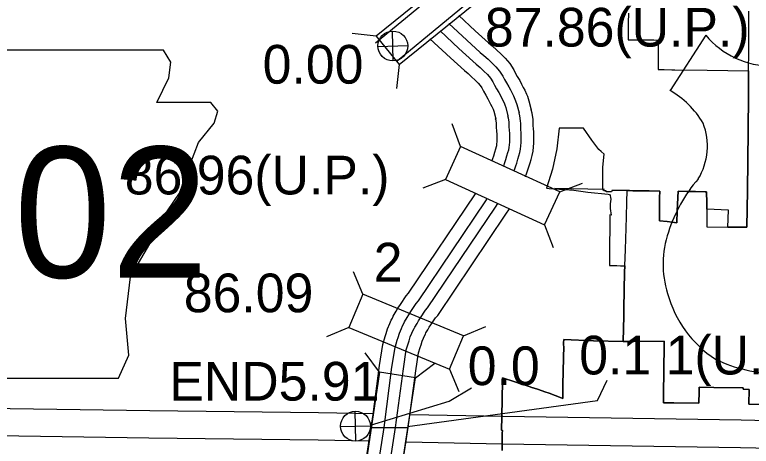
# Model space of a CAD drawing. Extents: x 77230 to 630905, y 790554 to 1662844.
# Drawn here: x 233840 to 249911, y 1585968 to 1595386 of the extents above; entities that cross this region are included whole.
import ezdxf

# ---------------------------------------------------------------- set-up
doc = ezdxf.new("R2010")
doc.units = 0
for name, color, linetype in [('Level 12', 7, 'Continuous'), ('Level 16', 7, 'Continuous'), ('Level 19', 7, 'Continuous'), ('Level 22', 7, 'Continuous'), ('Level 23', 7, 'Continuous'), ('Level 24', 7, 'Continuous'), ('Level 25', 7, 'Continuous'), ('Level 29', 7, 'Continuous'), ('Level 31', 7, 'Continuous'), ('Level 32', 7, 'Continuous'), ('Level 34', 7, 'Continuous')]:
    doc.layers.add(name, color=color, linetype=linetype)

msp = doc.modelspace()

# ---------------------------------------------------------------- linework, layer by layer
at = {"layer": 'Level 12'}
for points in [[(247229, 1595417), (247225, 1595210), (247225, 1594841), (247770, 1594836), (247783, 1594836), (247847, 1594834), (247882, 1594835), (247882, 1594189), (248012, 1594188), (248177, 1594185), (248242, 1594185), (248950, 1594173), (249851, 1594159), (249851, 1594021), (249848, 1593627), (249841, 1592853), (249831, 1591548), (249814, 1590748), (249401, 1590750), (249413, 1591121), (248943, 1591146), (248940, 1591278), (248934, 1591522), (248907, 1591522), (248698, 1591526), (248509, 1591529), (248314, 1591532), (248314, 1591532), (248297, 1591103), (248285, 1590847), (248188, 1590862), (248075, 1590872), (247906, 1590885), (247907, 1590919), (247907, 1590990), (247909, 1591118), (247910, 1591193), (247910, 1591268), (247912, 1591390), (247913, 1591539), (247681, 1591542), (247554, 1591543), (247479, 1591544), (247404, 1591545)], [(249831, 1591548), (249841, 1592853), (249848, 1593627), (249851, 1594021), (249851, 1594159), (249855, 1594592), (249860, 1595269), (249861, 1595465)], [(247404, 1591545), (247329, 1591546), (247254, 1591547), (247207, 1591548), (247179, 1591548), (247104, 1591549), (247029, 1591550), (246954, 1591551), (246866, 1591552), (246866, 1591544), (246865, 1591520), (246828, 1591520), (246747, 1591521), (246747, 1591543), (246701, 1591543), (246688, 1591559), (246674, 1591577), (246671, 1592002), (246671, 1592006), (246671, 1592061), (246699, 1592344), (246635, 1592402), (246582, 1592448), (246430, 1592651), (246250, 1592907), (246122, 1592907), (245865, 1592907), (245718, 1592909), (245669, 1592462), (245577, 1592017), (245441, 1591603), (245502, 1591597), (245846, 1591573), (245944, 1591567), (245992, 1591565), (246191, 1591532), (246347, 1591512), (246788, 1591467), (246817, 1591463), (246833, 1591441), (246842, 1591395), (246845, 1591363), (246833, 1591262), (246834, 1591159), (246853, 1591015), (246828, 1591017), (246826, 1590909), (246825, 1590829), (246824, 1590750), (246823, 1590670), (246822, 1590590), (246821, 1590510), (246820, 1590430), (246819, 1590350), (246818, 1590270), (246817, 1590190), (246817, 1590110), (246816, 1590030), (246815, 1589950), (246815, 1589914), (246895, 1589912), (246954, 1589911), (246975, 1589911), (247055, 1589909), (247150, 1589905), (247144, 1589767), (247144, 1589717), (247142, 1589618), (247141, 1589538), (247139, 1589458), (247138, 1589378), (247137, 1589298), (247135, 1589218), (247134, 1589138), (247132, 1589058), (247131, 1588978), (247130, 1588940), (247130, 1588898), (247128, 1588818), (247118, 1588255), (246466, 1588270), (245821, 1588296), (245817, 1588223), (245818, 1588093), (245812, 1587953), (245813, 1587823), (245807, 1587671), (245804, 1587526), (245801, 1587388), (245797, 1587013), (245766, 1587026), (245505, 1587128), (245410, 1587159), (245269, 1587205), (245155, 1587242), (245147, 1587245), (245041, 1587280), (244902, 1587325), (244895, 1587327), (244733, 1587380)], [(250223, 1586879), (249861, 1586887), (249867, 1587206), (249735, 1587212), (249736, 1587244), (249095, 1587254), (248773, 1587259), (248773, 1587231), (248772, 1587161), (248768, 1586906), (248225, 1586917), (247995, 1586919), (247996, 1587026), (247997, 1587161), (247998, 1587296), (248000, 1587431), (248002, 1587564), (248003, 1587699), (248006, 1587835), (248008, 1587969), (248009, 1588107), (248010, 1588265), (247351, 1588253), (247118, 1588255), (247128, 1588818), (247130, 1588898), (247130, 1588940), (247131, 1588978), (247132, 1589058), (247134, 1589138), (247135, 1589218), (247137, 1589298), (247138, 1589378), (247139, 1589458), (247141, 1589538), (247142, 1589618), (247144, 1589717), (247144, 1589767), (247150, 1589905), (247166, 1590259), (247181, 1590727), (247189, 1590977), (247199, 1591298), (247207, 1591548), (247254, 1591547), (247329, 1591546), (247404, 1591545), (247479, 1591544), (247554, 1591543), (247681, 1591542), (247913, 1591539), (247912, 1591390), (247910, 1591268), (247910, 1591193), (247909, 1591118), (247907, 1590990), (247907, 1590919), (247906, 1590885), (248075, 1590872), (248188, 1590862), (248285, 1590847), (248297, 1591103), (248314, 1591532), (248314, 1591532), (248509, 1591529), (248698, 1591526), (248907, 1591522), (248934, 1591522), (248940, 1591278), (248943, 1591146), (248943, 1591103), (248942, 1590973), (248940, 1590758), (249401, 1590750), (249814, 1590748), (249831, 1591548)], [(245807, 1587671), (245813, 1587823), (245812, 1587953), (245818, 1588093), (245817, 1588223), (245821, 1588296), (246466, 1588270), (247118, 1588255), (247351, 1588253), (248010, 1588265), (248009, 1588107), (248008, 1587969), (248006, 1587835), (248003, 1587699), (248002, 1587564), (248000, 1587431), (247998, 1587296), (247997, 1587161), (247996, 1587026), (247995, 1586919), (248225, 1586917), (248768, 1586906), (248772, 1587161), (248773, 1587231), (248773, 1587259), (249095, 1587254), (249736, 1587244), (249735, 1587212), (249867, 1587206), (249861, 1586887), (250223, 1586879)], [(244473, 1585878), (244475, 1585984), (244479, 1586255), (244480, 1586316), (244459, 1586317), (244466, 1586618), (244483, 1587389), (244484, 1587461), (244504, 1587455), (244733, 1587380), (244895, 1587327), (244902, 1587325), (245041, 1587280), (245147, 1587245), (245155, 1587242), (245269, 1587205), (245410, 1587159), (245505, 1587128), (245766, 1587026), (245797, 1587013), (245801, 1587388), (245804, 1587526), (245807, 1587671)], [(244733, 1587380), (244504, 1587455), (244484, 1587461), (244483, 1587389), (244466, 1586618), (244459, 1586317), (244480, 1586316), (244479, 1586255), (244475, 1585984), (244473, 1585878)]]:
    msp.add_lwpolyline(points, dxfattribs=at)
at = {"layer": 'Level 16'}
msp.add_lwpolyline([(246706, 1591573), (245626, 1591590)], dxfattribs=at)
at = {"layer": 'Level 19'}
for p, q in [((241729, 1594918), (241204, 1594973)), ((242228, 1594303), (242174, 1593778)), ((243570, 1592509), (243385, 1593004)), ((243570, 1592509), (243385, 1593004)), ((243241, 1591789), (242746, 1591604)), ((243241, 1591789), (242746, 1591604)), ((245731, 1591522), (246226, 1591707)), ((245731, 1591522), (246226, 1591707)), ((245402, 1590802), (245587, 1590307)), ((241437, 1589289), (241235, 1589777)), ((241134, 1588557), (240646, 1588355)), ((243632, 1588380), (244120, 1588582)), ((241800, 1587583), (241486, 1588007)), ((242583, 1587465), (243008, 1587779)), ((243329, 1587648), (243532, 1587160))]:
    msp.add_line(p, q, dxfattribs=at)
for points in [[(242228, 1594303), (244074, 1595800), (243575, 1596415), (241729, 1594918)], [(243241, 1591789), (245402, 1590802), (245731, 1591522), (243570, 1592509)], [(243632, 1588380), (241437, 1589289), (241134, 1588557), (243329, 1587648)], [(241800, 1587583), (241448, 1585233), (242231, 1585116), (242583, 1587465)]]:
    msp.add_lwpolyline(points, close=True, dxfattribs=at)
at = {"layer": 'Level 22'}
for points in [[(241711, 1594769), (243884, 1596567)], [(242182, 1594380), (244092, 1595960)], [(236791, 1586745), (232215, 1586809)], [(241662, 1586674), (240472, 1586698), (236791, 1586745)], [(257681, 1586377), (255038, 1586411), (252389, 1586475), (249688, 1586535), (244488, 1586615), (242468, 1586657)], [(236770, 1586145), (232508, 1586208), (232304, 1586209), (231553, 1586212)], [(241555, 1586076), (240462, 1586098), (236770, 1586145)], [(257374, 1585781), (255027, 1585811), (252375, 1585875), (249677, 1585935), (244477, 1586015), (242381, 1586059)]]:
    msp.add_lwpolyline(points, dxfattribs=at)
at = {"layer": 'Level 23'}
msp.add_lwpolyline([(241620, 1586379), (241663, 1586658)], dxfattribs=at)
at = {"layer": 'Level 24'}
msp.add_lwpolyline([(230240, 1594615), (230582, 1592331), (230430, 1588867), (230735, 1588677), (231306, 1588677), (231306, 1587458), (236102, 1587458), (236330, 1587953), (236254, 1588753), (236368, 1589666), (236787, 1590389), (237053, 1590922), (237434, 1591493), (237663, 1592102), (237853, 1592597), (238195, 1593016), (238272, 1593282), (238119, 1593473), (236939, 1593473), (237206, 1594006), (237244, 1594348), (237086, 1594611)], close=True, dxfattribs=at)
at = {"layer": 'Level 25'}
msp.add_line((248918, 1594939), (248139, 1593735), dxfattribs=at)
for centre, radius, start, end in [((250369, 1596159), 1896, 220.075, 319.6701), ((247121, 1591986), 2024, 30.7809, 59.9883), ((247567, 1592520), 1387, 328.8105, 21.2108), ((251194, 1589676), 3236, 138.9565, 162.6913), ((250126, 1589941), 2138, 160.9576, 197.3819), ((250474, 1589947), 2474, 195.1074, 237.1312), ((250520, 1590727), 3177, 244.0771, 269.5779)]:
    msp.add_arc(centre, radius, start, end, dxfattribs=at)
at = {"layer": 'Level 29'}
for points in [[(243531, 1595366), (243888, 1595034), (244179, 1594771), (244259, 1594704), (244358, 1594614), (244444, 1594530), (244538, 1594439), (244641, 1594318), (244727, 1594184), (244768, 1594102), (244806, 1594038), (244859, 1593950), (244901, 1593874), (244936, 1593800), (244968, 1593741), (245009, 1593650), (245027, 1593605), (245061, 1593506), (245110, 1593310)], [(243531, 1595366), (243888, 1595034), (244179, 1594771), (244259, 1594704), (244358, 1594614), (244444, 1594530), (244538, 1594439), (244641, 1594318), (244727, 1594184), (244768, 1594102), (244806, 1594038), (244859, 1593950), (244901, 1593874), (244936, 1593800), (244968, 1593741), (245009, 1593650), (245027, 1593605), (245061, 1593506), (245110, 1593310)], [(243313, 1595194), (243703, 1594831), (243998, 1594564), (244077, 1594497), (244170, 1594413), (244252, 1594333), (244337, 1594250), (244420, 1594154), (244487, 1594048), (244527, 1593969), (244571, 1593897), (244620, 1593814), (244656, 1593749), (244691, 1593675), (244722, 1593619), (244756, 1593542), (244769, 1593510), (244797, 1593428), (244844, 1593243)], [(243313, 1595194), (243703, 1594831), (243998, 1594564), (244077, 1594497), (244170, 1594413), (244252, 1594333), (244337, 1594250), (244420, 1594154), (244487, 1594048), (244527, 1593969), (244571, 1593897), (244620, 1593814), (244656, 1593749), (244691, 1593675), (244722, 1593619), (244756, 1593542), (244769, 1593510), (244797, 1593428), (244844, 1593243)], [(243120, 1595032), (243534, 1594647), (243834, 1594376), (243912, 1594309), (243998, 1594231), (244078, 1594154), (244155, 1594079), (244219, 1594005), (244270, 1593924), (244308, 1593848), (244356, 1593768), (244403, 1593689), (244433, 1593635), (244468, 1593561), (244498, 1593507), (244526, 1593444), (244535, 1593423), (244557, 1593358), (244601, 1593181)], [(243120, 1595032), (243534, 1594647), (243834, 1594376), (243912, 1594309), (243998, 1594231), (244078, 1594154), (244155, 1594079), (244219, 1594005), (244270, 1593924), (244308, 1593848), (244356, 1593768), (244403, 1593689), (244433, 1593635), (244468, 1593561), (244498, 1593507), (244526, 1593444), (244535, 1593423), (244557, 1593358), (244601, 1593181)], [(242901, 1594860), (243348, 1594444), (243652, 1594169), (243731, 1594103), (243810, 1594031), (243886, 1593957), (243954, 1593890), (243997, 1593840), (244030, 1593788), (244067, 1593715), (244120, 1593627), (244165, 1593553), (244188, 1593509), (244223, 1593436), (244251, 1593385), (244273, 1593336), (244277, 1593327), (244293, 1593280), (244335, 1593114)], [(244987, 1591851), (244988, 1591855), (245009, 1591916), (245035, 1592000), (245058, 1592067), (245085, 1592157), (245106, 1592229), (245131, 1592313), (245151, 1592411), (245160, 1592501), (245165, 1592586), (245166, 1592678), (245168, 1592735), (245165, 1592823), (245159, 1592901), (245156, 1592958), (245155, 1593020), (245150, 1593102), (245129, 1593235), (245111, 1593308)], [(244260, 1592203), (244275, 1592249), (244296, 1592310), (244317, 1592384), (244340, 1592460), (244355, 1592508), (244359, 1592530), (244363, 1592565), (244366, 1592611), (244366, 1592695), (244367, 1592739), (244366, 1592779), (244361, 1592846), (244356, 1592929), (244355, 1592989), (244354, 1593015), (244344, 1593076), (244334, 1593116)], [(244513, 1592088), (244536, 1592163), (244558, 1592226), (244581, 1592306), (244603, 1592380), (244622, 1592441), (244632, 1592489), (244637, 1592543), (244640, 1592603), (244641, 1592690), (244643, 1592738), (244641, 1592794), (244635, 1592865), (244631, 1592939), (244630, 1593000), (244627, 1593045), (244614, 1593131), (244601, 1593182)], [(244737, 1591972), (244747, 1592001), (244774, 1592085), (244796, 1592150), (244821, 1592235), (244843, 1592308), (244865, 1592380), (244879, 1592452), (244886, 1592523), (244890, 1592595), (244891, 1592684), (244893, 1592736), (244891, 1592808), (244885, 1592882), (244881, 1592948), (244880, 1593010), (244876, 1593072), (244859, 1593181), (244844, 1593242)], [(241658, 1586659), (241800, 1587731), (241870, 1588189), (241924, 1588366), (241944, 1588426), (241976, 1588531), (242024, 1588646), (242056, 1588719), (242080, 1588762), (242098, 1588806), (242164, 1588913), (242202, 1588983), (242257, 1589064), (242380, 1589252), (242432, 1589312), (243893, 1591480), (243896, 1591484)], [(241898, 1586379), (242072, 1587692), (242139, 1588127), (242186, 1588282), (242206, 1588342), (242235, 1588438), (242277, 1588537), (242303, 1588597), (242329, 1588644), (242344, 1588681), (242402, 1588775), (242437, 1588839), (242486, 1588911), (242600, 1589086), (242651, 1589144), (244122, 1591327), (244158, 1591382)], [(242151, 1586379), (242320, 1587657), (242383, 1588072), (242424, 1588205), (242444, 1588266), (242471, 1588354), (242506, 1588439), (242528, 1588487), (242555, 1588536), (242567, 1588567), (242618, 1588649), (242651, 1588709), (242694, 1588773), (242800, 1588935), (242850, 1588992), (244329, 1591188), (244383, 1591268)], [(242423, 1586379), (242592, 1587618), (242652, 1588010), (242686, 1588121), (242706, 1588182), (242730, 1588261), (242759, 1588330), (242774, 1588365), (242803, 1588418), (242813, 1588442), (242856, 1588511), (242885, 1588565), (242923, 1588620), (243020, 1588769), (243069, 1588825), (244558, 1591035), (244633, 1591148)], [(240191, 1578657), (241236, 1583910), (241620, 1586379), (242423, 1586379)], [(240461, 1578603), (241506, 1583862), (241898, 1586379)], [(240706, 1578554), (241753, 1583819), (242151, 1586379)], [(242377, 1586041), (242423, 1586379)], [(240976, 1578501), (242023, 1583771), (242377, 1586041)]]:
    msp.add_lwpolyline(points, dxfattribs=at)
at = {"layer": 'Level 31'}
msp.add_lwpolyline([(241606, 1586428), (243316, 1586949), (243807, 1587247)], dxfattribs=at)
at = {"layer": 'Level 32'}
msp.add_lwpolyline([(242409, 1586399), (246558, 1586964), (246766, 1587410)], dxfattribs=at)
at = {"layer": 'Level 34'}
for p, q in [((242098, 1594378), (242083, 1595029)), ((241765, 1594696), (242416, 1594711)), ((241283, 1586081), (241268, 1586732)), ((240950, 1586399), (241601, 1586414))]:
    msp.add_line(p, q, dxfattribs=at)
for centre in [(242091, 1594704), (241275, 1586406)]:
    msp.add_circle(centre, 326, dxfattribs=at)

# ---------------------------------------------------------------- texts
at = {"layer": 'Level 19'}
msp.add_text('2', height=845, dxfattribs=at).set_placement((241672, 1589563))
at = {"layer": 'Level 24'}
msp.add_text('102', height=2851.2, dxfattribs=at).set_placement((231705, 1589650))
at = {"layer": 'Level 31'}
for s, p in [('0.0', (243725, 1587302)), ('END5.91', (237214, 1586965))]:
    msp.add_text(s, height=844.8, dxfattribs=at).set_placement(p)
at = {"layer": 'Level 32'}
for s, p in [('87.86(U.P.)', (244099, 1594691)), ('0.00', (239250, 1593882)), ('86.96(U.P.)', (236241, 1591464)), ('86.09', (237529, 1588893)), ('0.1 1(U.P.)', (246158, 1587535))]:
    msp.add_text(s, height=844.8, dxfattribs=at).set_placement(p)

doc.saveas('drawing.dxf')
